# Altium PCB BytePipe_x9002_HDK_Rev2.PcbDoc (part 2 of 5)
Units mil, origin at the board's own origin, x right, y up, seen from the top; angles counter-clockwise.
Board outline 4250 x 4250 mil, 8 copper layers (Top Layer, L2-GND, L3-SIG, L4-GND, L5-PWR, L6-SIG, L7-GND, Bottom Layer), stack 63 mil thick; 296 components, 250 nets, 1198 pads, 2326 vias.
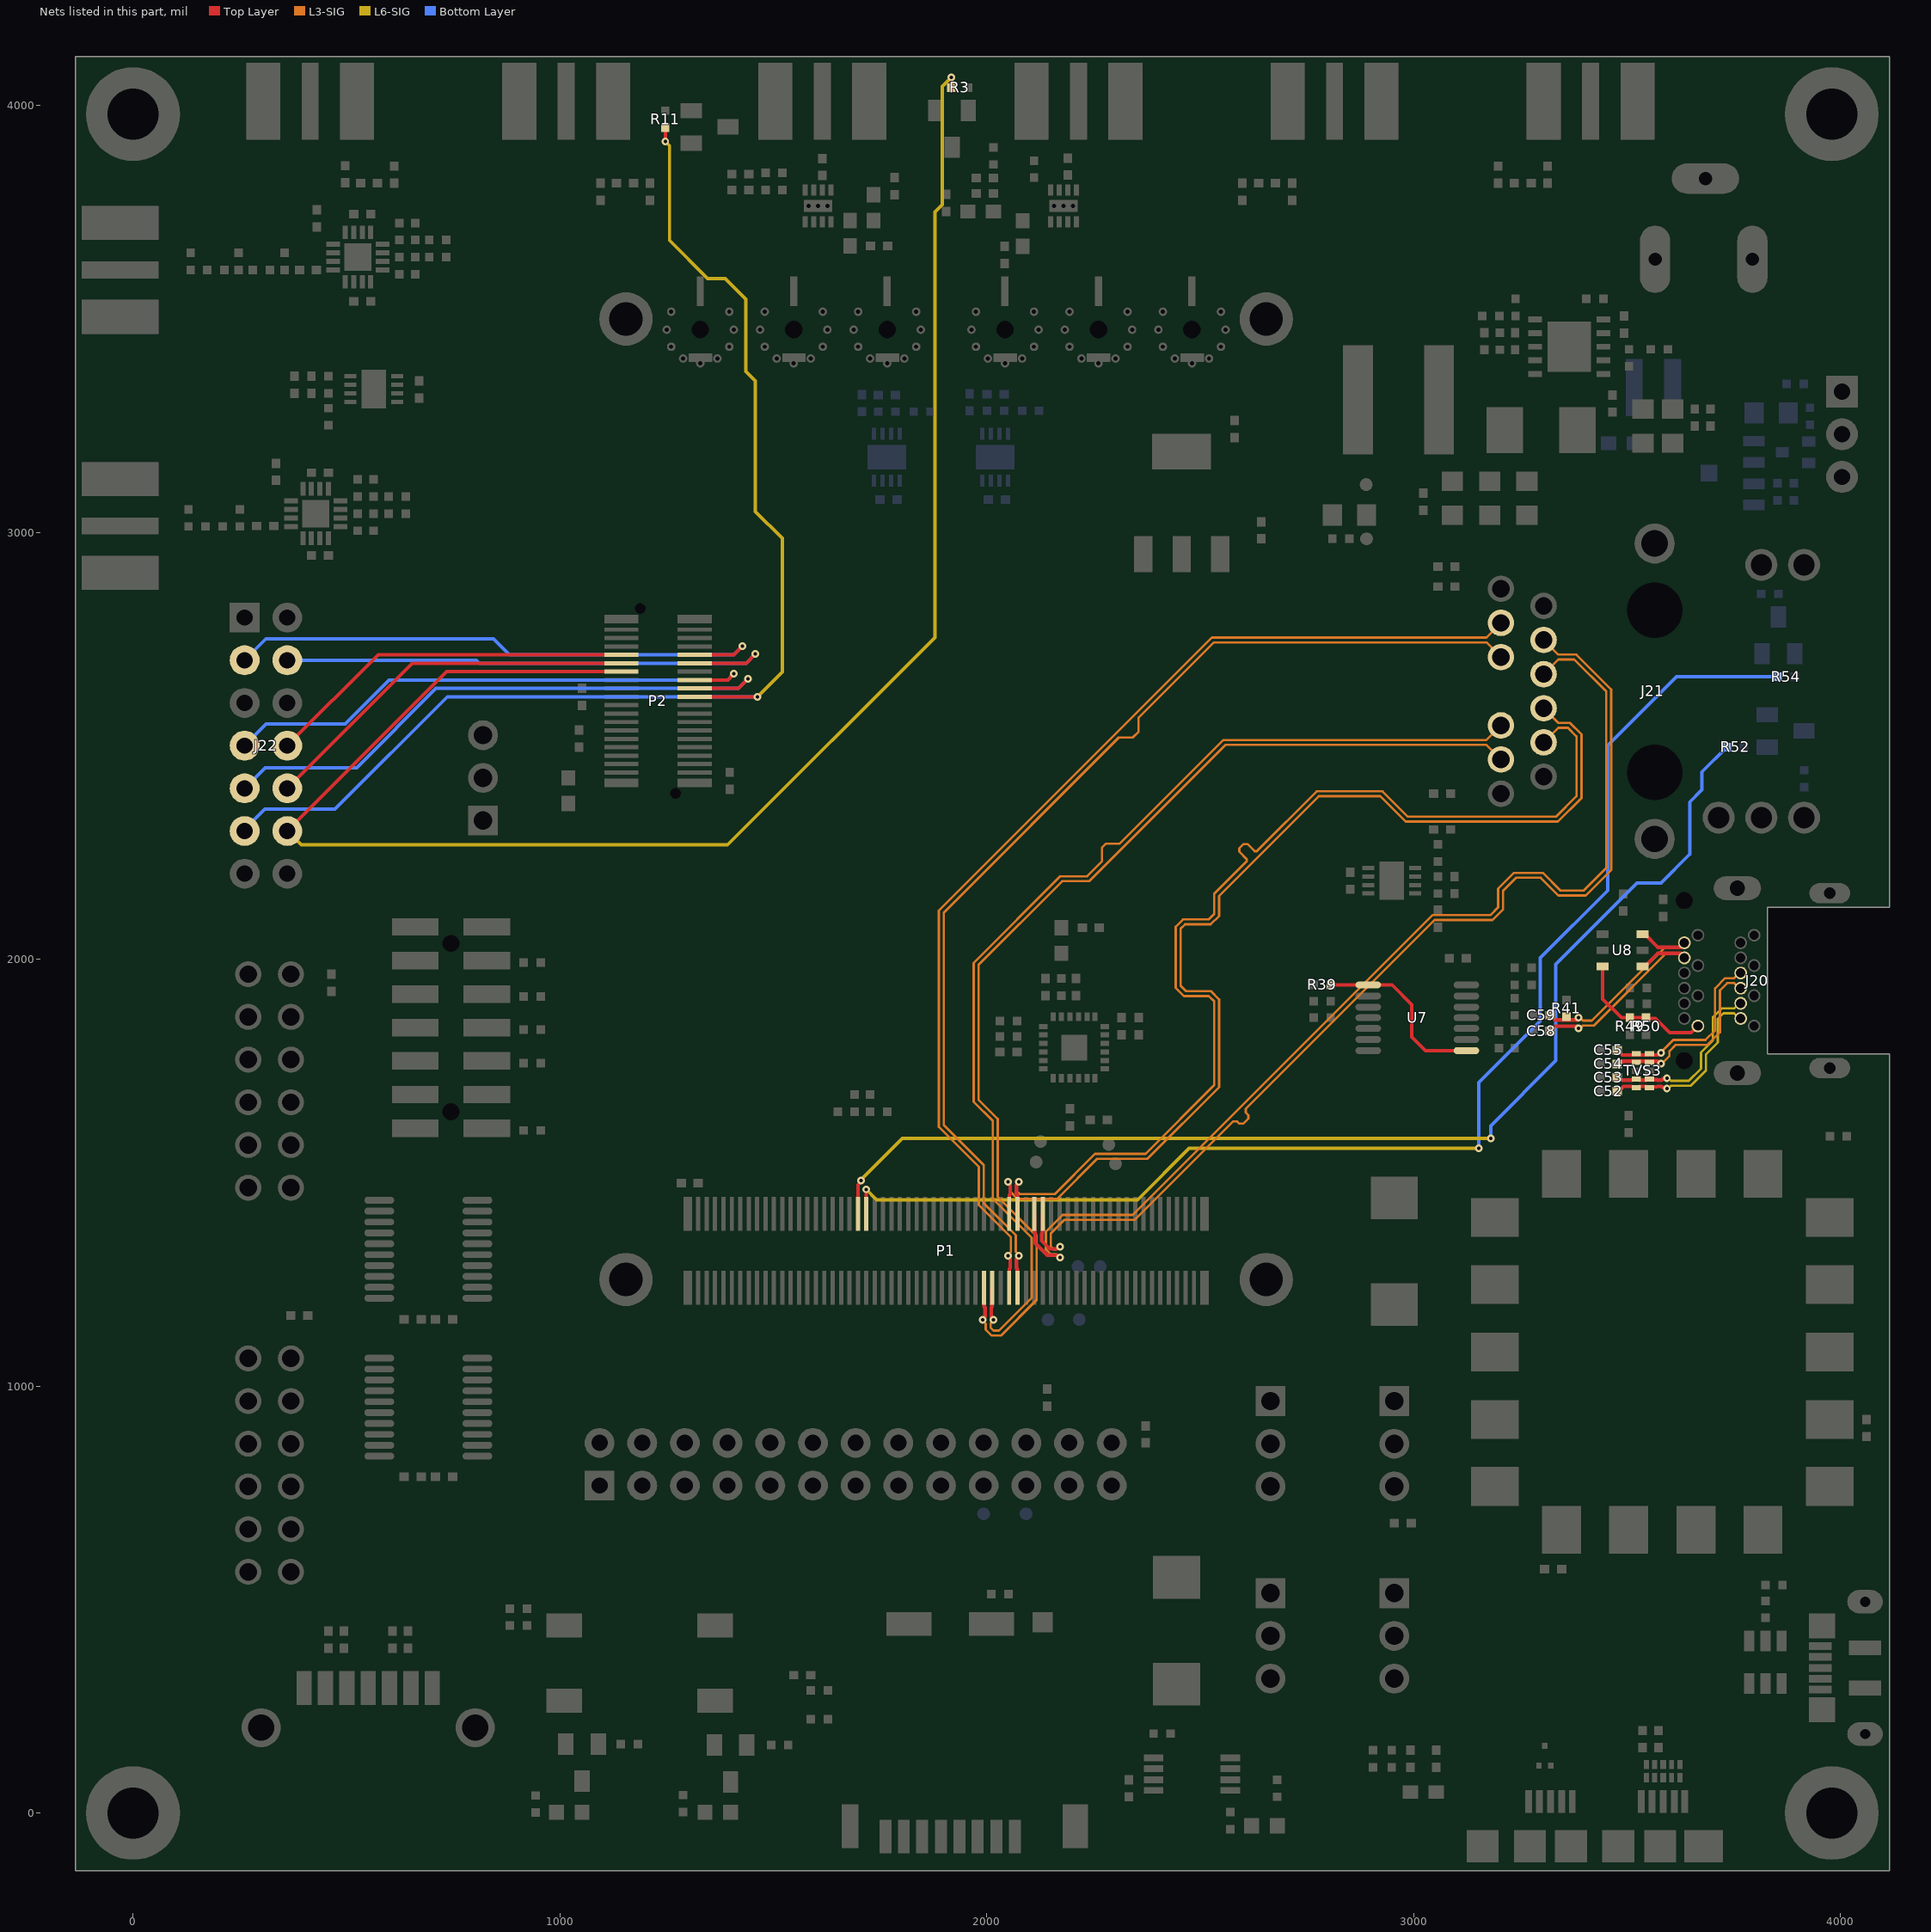
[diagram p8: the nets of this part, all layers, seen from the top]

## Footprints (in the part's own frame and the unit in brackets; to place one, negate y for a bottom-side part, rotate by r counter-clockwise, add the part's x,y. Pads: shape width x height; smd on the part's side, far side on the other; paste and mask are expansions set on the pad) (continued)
SM/SOT323_A [mil]
  rect 24x31 smd mask+3: 1(-25,-31) 2(25,-31) 3(0,31)
  silkscreen extent -45,-5 45,30
SM/SWITCH/E-SWITCH/SPST [mil] "SWITCH TACTILE SPST-NO 0.05A 12V"
  rect 84x56 smd paste+0 mask+3: 1(0,0) 2(354,0) 3(0,176) 4(354,176)
  silkscreen extent -55,-40 409,216, body extent -20,-30 374,206, height 172
SM/TESTPOINT/30MIL [mil]
  round 30 smd paste-15 mask+2: 1(0,0)
SM/TSOP-6_A [mil] "Built for the IP422OCZ6"
  rect 18x28 smd mask+3: 1(37.5,47) 2(0,47) 3(-37.5,47) 4(-37.5,-47) 5(0,-47) 6(37.5,-47)
  silkscreen extent -65,-75 65,75, body extent -57,-46 57,46, height 39
SM/TSSOP14_5X6.4MM_A [mil]
  oval 16x60 smd mask+3: 1(-77,-115) 2(-51,-115) 3(-25,-115) 4(0,-115) 5(25,-115) 6(51,-115) 7(77,-115) 8(77,115) 9(51,115) 10(25,115) 11(0,115) 12(-25,115) 13(-51,115) 14(-77,115)
  silkscreen extent -115,-165 115,165, body extent -98,-126 98,126, height 47
SM/TSSOP20_6.5X6.4MM [mil]
  oval 16x70 smd mask+3: 1(0,0) 2(25.5,0) 3(51,0) 4(76.5,0) 5(102,0) 6(127.5,0) 7(153,0) 8(178.5,0) 9(204,0) 10(229.5,0) 11(229.5,230) 12(204,230) 13(178.5,230) 14(153,230) 15(127.5,230) 16(102,230) 17(76.5,230) 18(51,230) 19(25.5,230) 20(0,230)
  silkscreen extent -25,-50 255,280, body extent -15,-14 245,244, height 47
SM/WSON10/4x4MM_A [mil] ".8mm lead pitch"
  rect 14x32 smd paste+0 mask+3: 1(-64,-80) 2(-32,-80) 3(0,-80) 4(32,-80) 5(64,-80) 6(64,80) 7(32,80) 8(0,80) 9(-32,80) 10(-64,80)
  rect 118x102 smd paste-10 mask+3: 11(0,0)
  silkscreen extent -85,-112 85,90
SWITCH/NIDEC/SPDT/AS1D-2M-10-Z [mil] "SWITCH SLIDE SPDT 50MA 48V"
  rect 75x75 hole 38: 1(0,0)
  round 75 hole 38: 2(0,-100) 3(0,-200)
  silkscreen extent -105,-290 106,99, body extent -98,-287 98,87, height 485

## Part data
C1 C4 C23 C27 C38 C39 C43 C47 C48 C67 C70 C71 C72 C75 C76 C82 C85 C88 C91: "CAP CER 4.7UF 10V X5R 0402", VOLT=10V
C2 C3 C5 C18 C77 C80 C83 C86 C89: "10µF ±20% 10V Ceramic Capacitor X5R 0402 (1005 Metric)", VOLT=10V
C6 C12 C13 C19 C21 C22: "CAP CER 100PF 50V C0G/NP0 0402", VOLT=50V
C7 C20: "CAP CER 1UF 16V X5R 0402", VOLT=16V
C24 C26 C28 C30 C31 C32 C33 C34 C35 C40 C41 C42 C44 C45 C46 C49 C50 C51 C52 C53 C54 C55 C56 C57 C58 C59 C60 C61 C62 C63 C64 C65 C66 C68 C69 C78 C79 C81 C84 C87 C90: "CAP CER 0.1UF 25V X7R 0402", VOLT=25V
C25 C29: "CAP CER 10000PF 50V X7R 0402", VOLT=50V
C36 C37: library part CAP_TANT-D, "CAP TANT 150UF 20% 10V 2917", VOLTS=10V
C73 C74 C97: library part CAP_CERAMIC_0402, "CAP CER 1000PF 50V C0G/NP0 0402", VOLT=50V
C92 C93 C94: "CAP CER 10UF 35V X5R 0805", VOLT=35V
C95 C104: VOLT=50V
C96: "CAP CER 0.1UF 50V X7R 0402", VOLT=50V
C98 C99 C100: "CAP CER 22UF 16V X5R 0805", VOLT=16V
C101: library part CAP_CERAMIC_0402, "CAP CER 10000PF 50V X7R 0402", VOLT=50V
C102: library part CAP_CERAMIC_0402, "CAP CER 47PF 50V C0G/NP0 0402", VOLT=50V
C103: library part CAP_CERAMIC_0402, "CAP CER 4700PF 50V X7R 0402", VOLT=50V
D1: "DIODE SCHOTTKY 60V 5A SMB"
J1: library part CON_100SP_1X3P_MLX_KK100, "Connector Header Through Hole 3 position 0.100\" (2.54mm).  Molex KK 100 Series."
J3 J5 J7 J9 J11 J13 J15 J16: "SMA board edge style, .250\" wide style"
J4 J6 J8 J10 J12 J14: "SMPM Connector Plug, Male Pin 50Ohm Surface Mount Solder. Based off of Amphenol 925-144J-51PT"
J17: "7 Position SATA Plug Connector Solder Surface Mount, Right Angle"
J18: "CONN RCPT USB3.1 MICRO B SMD R/A"
J19: library part CON_HIROSE_MICRO-SD_HINGED, "10 (8 + 2) Position Card Connector Secure Digital - microSD™ Surface Mount, Right Angle Gold"
J20: "DisplayPort, Mini  Receptacle Connector 20 Position Through Hole, Right Angle.."
J21: "1 Port RJ45 Magjack Connector Through Hole 10/100/1000 Base-T, AutoMDIX"
J22: "Connector Header Through Hole 14 position 0.100\" (2.54mm)"
J23: "PIN HEADER, DOUBLE ROW 26 PIN, S"
J24: "Connector Header Surface Mount 14 position 0.079\" (2.00mm)"
J25: "Wurth DC power jack, 2.1mm pin, right angle"
J26: "USB MICRO-B RIGHT ANGLE, MOLEX 1051640001"
J28 J31: "Header, 100 mil, 2x6, Right Angle, PMOD pin out."
JP1 JP2 JP3 JP4: "PIN HEADER, SINGLE ROW 3 PIN STR"
L1 L7 L9 L10: "120 Ohms @ 100MHz 1 Power Line Ferrite Bead 0603 (1608 Metric) 3A 25mOhm"
L2 L3 L5 L6 R10 R39 R40 R42 R100 R101: "RES SMD 0 OHM JUMPER 1/10W 0402"
L4 L8: "FIXED IND 68NH 300MA 800 MOHM"
L11: "Fixed Inductors 4.7uH 20% 5.1A 44.1mOhms AEC-Q200"
LED1 LED2 LED3: "LED-0603"
MH1 MH2 MH3 MH4: "125 mil pad / 78 mil hole"
MH5 MH6 MH7 MH8: "220 mil pad / 120 mil hole (#4 Pan Head Screw)"
P1: library part CON_JAE_WR-120S-VFH30-N1, "0.5 mm pitch, 120 Position Connector Receptacle, Center Strip Contacts Surface Mount Gold."
P2: library part CON_JAE_WR-40SB-VFH30-N1, "0.5 mm pitch, 40 Position Connector Receptacle, Center Strip Contacts Surface Mount Gold, with Alignment Pins."
Q1 Q2 Q3 Q4 Q5 Q6: "Bipolar (BJT) Transistor NPN 40V 200mA 300MHz 300mW Surface Mount SOT-23-3 (TO-236)"
Q7: library part FET_P-CHANNEL_PPAK-SO-8, "P-Channel 20 V 60A (Tc) 6.25W (Ta), 104W (Tc) Surface Mount PowerPAK® SO-8"
Q8: "FET, N-Channel, SC70/SOT323"
R1 R3 R4 R11 R77 R78 R79 R86 R88: "RES SMD 10K OHM 1% 1/10W 0402"
R6 R7 R18 R19: "RES SMD 127 OHM 1% 1/10W 0402"
R8 R9 R12 R20 R21 R22 R37 R49 R55 R56 R57 R58 R59 R61: "RES SMD 39 OHM 1% 1/10W 0402"
R13 R14 R15 R23 R24 R43 R44: "RES 49.9 OHM 1% 1/10W 0402"
R16 R17 R25 R26: "RES SMD 150 OHM 1% 1/10W 0402"
R27 R83: "RES SMD 1K OHM 1% 1/10W 0402"
R30 R31 R51 R53 R65 R69: "RES SMD 240 OHM 1% 1/10W 0402"
R32: "RES 2 OHM 1% 1/10W 0402 SMD"
R35 R36 R62: "RES SMD 4.7K OHM 1% 1/10W 0402"
R38 R41 R50 R52 R54 R60 R68 R70 R85: "RES SMD 100K OHM 1% 1/10W 0402"
R45 R46: "RES SMD 1M OHM 1% 1/10W 0402"
R47: "RES SMD 1.5K OHM 1% 1/10W 0402"
R48: "RES SMD 2.49K OHM 1% 1/10W 0402"
R66: "RES 120K OHM 1% 1/10W 0402 SMD"
R67 R72: "RES SMD 78.7K OHM 1% 1/10W 0402"
R71: "RES SMD 140K OHM 1% 1/10W 0402"
R73 R75: "RES SMD 200K OHM 1% 1/10W 0402"
R74 R76: "RES SMD 64.9K OHM 1% 1/10W 0402"
R80 R102 R103: "DNP"
R81: "RES SMD 0 OHM JUMPER 1/8W 0805"
R82: "RES SMD 52.3K OHM 1% 1/10W 0402"
R84: "RES SMD 2 KOHM 1% 1/5W 0402"
R87: "RES SMD 16.9K OHM 1% 1/10W 0402"
SW1: "Tactile Switch SPST-NO Top Actuated Surface Mount"
SW2: library part SWITCH_SLIDE_NIDEC_SPDT, "SWITCH SLIDE SPDT 50MA 48V"
TVS1 TVS3: "TVS DIODE 5.5V 14V 10SON"
TVS2: "TVS DIODE 5.5V 8V SOT3"
U1 U2: "RF Amplifier 50-4000MHz NF .66dB Gain 16.5dB @1.9GHz"
U3 U4: "IC CLK BUFFER 1:4 7GHZ 16LFCSP"
U5: "Power Switch/Driver 1:1 N-Channel 1.5A 8-MSOP"
U6: "IC Programable Clock Generator"
U7: "1/1 Transceiver Full LVDS 14-TSSOP"
U8: "Dual USB ESD Protection"
U9: "SMT Programming module for Xilinx FPGAs."
U10 U11: "IC TRNSLTR BIDIRECTIONAL 20VQFN"
U12: "Clamp Ipp Tvs Diode Surface Mount SOT-23-6."
U13: "Linear Voltage Regulator IC 3.3V Output 1A SOT-223-3"
U14 U15 U16 U17: "Linear Voltage Regulator IC  1 Output  500mA 8-LFCSP-WD (3x3)"
U18: "4.5-V to 60-V Input, 5-A, Step-Down DC-DC Converter with Soft-Start and Eco-mode"

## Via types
v1: diameter 18, hole 8, Top Layer to Bottom Layer, tented both sides, 2283 vias
v2: diameter 20, hole 10, Top Layer to Bottom Layer, tented both sides, 39 vias
v3: diameter 16, hole 8, Top Layer to Bottom Layer, tented both sides, 4 vias

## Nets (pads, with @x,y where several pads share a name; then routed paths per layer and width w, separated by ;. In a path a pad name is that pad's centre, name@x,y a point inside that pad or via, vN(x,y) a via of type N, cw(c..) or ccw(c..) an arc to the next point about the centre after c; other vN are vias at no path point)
AGPIO_1: J22.7 P2.16 | length 1313.8
  Top Layer w8: P2.16@1316.61,2654.21 1393.09,2654.21 1407.88,2669 v1(1408,2669)
  Bottom Layer w8: J22.7@261.5,2500.5 312.25,2551.25 497.29,2551.25 600.25,2654.21 1393.21,2654.21 v1(1408,2669)
AGPIO_2: J22.8 P2.09 | length 870
  Top Layer w8: J22.8@361.5,2500.5 574.27,2713.27 P2.09@1143.39,2713.27
AGPIO_3: J22.9 P2.18 | length 1419.4
  Top Layer w8: P2.18@1316.61,2634.53 1418.53,2634.53 v1(1441,2657)
  Bottom Layer w8: J22.9@261.5,2400.5 309.93,2448.93 524.35,2448.93 709.95,2634.53 1418.53,2634.53 v1(1441,2657)
AGPIO_4: J22.10 P2.11 | length 903.3
  Top Layer w8: J22.10@361.5,2400.5 654.58,2693.58 P2.11@1143.39,2693.58
AGPIO_5: J22.11 P2.20 R11.1 | length 2975.3
  Top Layer w8: J22.11@261.5,2300.5 J22.11@261.5,2304.37 ; v1(1247,3916) R11.1@1247,3948 ; P2.20@1316.61,2614.84 v1(1463.16,2614.84)
  L6-SIG w8: v1(1247,3916) 1257,3906 1257,3684 1346,3595 1387,3595 1436,3546 1436,3377.31 1458,3355.31 1458,3049 1521,2986 1521,2672.68 v1(1463.16,2614.84)
  Bottom Layer w8: J22.11@261.5,2304.37 308.55,2351.41 472.88,2351.41 736.31,2614.84 v1(1463.16,2614.84)
AGPIO_6: J22.12 P2.13 R3.1 | length 4020.6
  Top Layer w8: J22.12@361.5,2300.5 734.9,2673.9 P2.13@1143.39,2673.9 ; R3.1@1917,4042 v1(1917,4066)
  L6-SIG w8: J22.12@361.5,2300.5 394,2268 1393,2268 1879,2754 1879,3751 1896,3768 1896,4045 v1(1917,4066)
AUXADC_0: J22.3 P2.10 | length 1331.1
  Top Layer w8: P2.10@1316.61,2713.27 1407.27,2713.27 v1(1428,2734)
  Bottom Layer w8: J22.3@261.5,2700.5 311.34,2750.34 844.64,2750.34 881.71,2713.27 1407.27,2713.27 v1(1428,2734)
AUXADC_1: J22.4 P2.12 | length 1258.5
  Top Layer w8: P2.12@1316.61,2693.58 1436.58,2693.58 v1(1458,2715)
  Bottom Layer w8: J22.4@361.5,2700.5 804.06,2700.5 810.97,2693.58 1436.58,2693.58 v1(1458,2715)
DP_HPD: J20.2 R49.2 R50.2 U8.3 | length 339.2
  Top Layer w8: U8.3@3443,1983.5 3443,1907 3487,1863 R49.2@3507,1863 R50.2@3545,1863 3547,1861 3567,1861 3600.26,1827.74 3650.26,1827.74 J20.2@3666.22,1843.7
DP_RE_N: R39.1 U7.1 U7.8 | length 426.3
  Top Layer w8: R39.1@2806,1940 U7.1@2894,1940 2950,1940 2996,1894 2996,1818 3028,1786 U7.8@3124,1786
DP_TX2_N: C55.2 J20.11 TVS3.5 TVS3.6 | length 427.7
  Top Layer w8.75: C55.2@3480,1787 3480,1785 3489.1,1775.9 3522.03,1775.9 TVS3.6@3524.5,1778.37 ; TVS3.6@3525.58,1775.9 3550.61,1775.9 TVS3.5@3553.08,1778.37 3555.58,1775.88 3571.95,1775.88 3577.08,1781 v1(3579.58,1781)
  L3-SIG w5.5: v1@3582,1784.38 3608.62,1811 3684,1811 3706.5,1833.5 3706.5,1932.01 3730.24,1955.75 3751.14,1955.75 3763.11,1967.72 J20.11@3766.61,1967.72
DP_TX2_P: C54.2 J20.9 TVS3.4 TVS3.7 | length 439.3
  Top Layer w8.75: C54.2@3480,1754.67 3481.3,1755.97 3481.3,1757.97 3483.62,1760.29 3490.89,1760.29 3491.75,1761.15 3522.03,1761.15 TVS3.7@3524.5,1758.68 ; TVS3.7@3525.58,1761.15 TVS3.4@3549.44,1761.15 ; TVS3.4@3549.47,1761.12 3550.64,1761.12 TVS3.4@3553.08,1758.68 3555.52,1761.12 3571.95,1761.12 3577.08,1756 v1(3579.58,1756)
  L3-SIG w5.5: v1@3582,1756 3582.1,1756 3599.75,1773.65 3599.75,1784.75 3614.5,1799.5 3688.76,1799.5 3718,1828.74 3718,1927.25 3735,1944.25 3751.14,1944.25 3763.11,1932.28 J20.9@3766.61,1932.28
DP_TX3_N: C53.2 J20.5 TVS3.2 TVS3.9 | length 420.2
  Top Layer w8.75: C53.2@3481,1723.33 3480,1723.33 3480,1721.33 3483.62,1717.71 3487.97,1717.71 3488.75,1716.92 3511.44,1716.92 3512.21,1717.69 3520.46,1717.69 TVS3.9@3522.08,1719.31 3527.08,1719.31 3529.55,1716.85 TVS3.2@3544.58,1716.85 ; TVS3.2@3553.08,1719.31 3554.71,1717.69 3570.58,1717.69 3571.43,1716.85 3581.65,1716.85 3584.56,1719.75 3591.85,1719.75 v1(3593.62,1721.52)
  L6-SIG w5.5: v1(3593.62,1721.52) 3596.84,1721.52 3603.09,1715.27 3610.87,1715.27 3645.02,1715.27 3673.5,1743.75 3673.5,1781.76 3701.5,1809.76 3701.5,1864.76 3721.62,1884.88 3751.14,1884.88 3763.11,1896.85 J20.5@3766.61,1896.85
DP_TX3_P: C52.2 J20.3 TVS3.1 TVS3.10 | length 415
  Top Layer w8.75: C52.2@3480,1691 3481,1691 3492.17,1702.17 3511.29,1702.17 3512.21,1701.25 3520.46,1701.25 TVS3.10@3522.08,1699.63 ; TVS3.10@3527.08,1699.63 3529.55,1702.1 TVS3.1@3544.58,1702.1 ; TVS3.1@3553.08,1699.63 3554.71,1701.25 3570.58,1701.25 3571.43,1702.1 3581.75,1702.1 3584.56,1699.29 3591.85,1699.29 v1(3593.62,1697.52)
  L6-SIG w5.5: v1(3593.62,1697.52) 3596.84,1697.52 3603.09,1703.77 3615.63,1703.77 3649.79,1703.77 3685,1738.99 3685,1777 3713,1805 3713,1860 3726.38,1873.38 3751.14,1873.38 3763.11,1861.42 J20.3@3766.61,1861.42
DPAUX_C_N: C59.2 J20.18 R41.1 U8.6 | length 496.9
  Top Layer w8.75: C59.2@3320,1869 3321,1869 3326.62,1863.38 3326.62,1863 3331.75,1857.88 v1@3385,1857.88 ; U8.6@3537,2058.5 3542,2058.5 3572.12,2028.38 J20.18@3625.58,2028.38
  L3-SIG w5.5: v1(3387,1863) 3389.72,1863 3396.47,1856.25 3417.87,1856.25 3588.24,2026.62 3619.25,2026.62 3631.22,2038.58 J20.18@3634.72,2038.58
DPAUX_C_P: C58.2 J20.16 U8.4 | length 496.9
  Top Layer w8.75: C58.2@3320,1832 3321,1832 3326.62,1837.62 3326.62,1838 3331.75,1843.12 v1@3385,1843.12 ; U8.4@3537,1983.5 3542,1983.5 3572.12,2013.62 J20.16@3625.58,2013.62
  L3-SIG w5.5: v1(3387,1838) 3389.72,1838 3396.47,1844.75 3422.63,1844.75 3593,2015.12 3619.25,2015.12 3631.22,2003.15 J20.16@3634.72,2003.15
ETH_LED0: P1.81 R52.2 | length 2776.9
  Top Layer w8: P1.81@1698.31,1403.61 1698.65,1403.96 1698.65,1472 1705.83,1479.18 v1(1705.83,1481.69)
  L6-SIG w8: v1(1705.83,1481.69) 1705.83,1483.25 1802.58,1580 v1(3181,1580)
  Bottom Layer w8: v1(3181,1580) 3181,1609.73 3333.68,1762.41 3333.68,1988.68 3524,2179 3580,2179 3647,2246 3647,2368 3676,2397 3676,2439 R52.2@3734,2497
ETH_LED1: P1.79 R54.2 | length 3086
  Top Layer w8: P1.79@1717.99,1403.61 v1(1718,1461)
  L6-SIG w8: v1(1718,1461) 1742.27,1436.73 2353.77,1436.73 2474.03,1557 v1(3153,1557)
  Bottom Layer w8: v1(3153,1557) 3153,1711 3297,1855 3297,2003 3455,2161 3455,2501 3616,2662 R54.2@3853,2662
ETH_MD1_N: J21.10 P1.50 | length 2558.1
  Top Layer w8.75: P1.50@2013.27,1230.39 2012.64,1229.76 2012.64,1185.88 2010.77,1184.01 2010.77,1163.07 2015.89,1157.95 v1(2015.89,1155.44)
  L3-SIG w5.5: v1(2015.89,1155.44) 2015.89,1152.72 2009.14,1145.97 2009.14,1137.17 2016.31,1130 2028.74,1130 2105.67,1206.94 2105.67,1347.32 2014.5,1438.49 2014.5,1621.24 1969.5,1666.24 1969.5,1991.5 2172.5,2194.5 2235.24,2194.5 2270,2229.26 2270,2261 2280,2271 2311.74,2271 2554.49,2513.75 3170.75,2513.75 J21.10@3205,2548 J21.10@3203,2548
ETH_MD1_P: J21.11 P1.52 | length 2561.8
  Top Layer w8.75: v1(1990.89,1155.44) 1990.89,1157.95 1996.02,1163.07 1996.02,1184.07 1994.21,1185.88 P1.52@1994.21,1235.87
  L3-SIG w5.5: v1(1990.89,1155.44) 1990.89,1152.72 1997.64,1145.97 1997.64,1132.41 2011.55,1118.5 2033.5,1118.5 2117.17,1202.17 2117.17,1352.08 2026,1443.26 2026,1626 1981,1671 1981,1986.74 2177.26,2183 2240,2183 2559.25,2502.25 3170.75,2502.25 J21.11@3205,2468
ETH_MD2_N: J21.5 P1.43 | length 2556.1
  Top Layer w8.75: P1.43@2072.32,1403.61 2071.7,1404.24 2071.7,1448.12 2069.86,1449.96 2069.86,1470.9 2075.01,1476.05 v1(2075.01,1478.56)
  L3-SIG w5.5: v1(2075.01,1478.56) 2075.01,1475.83 2068.26,1469.08 2068.26,1458.74 2077,1450 2160,1450 2254,1544 2372.07,1544 2533,1704.93 2533,1901.26 2520.5,1913.76 2462.24,1913.76 2443,1933 2443,2076.26 2460,2093.26 2520,2093.26 2533,2106.26 2533,2153.26 2609.59,2229.85 2609.59,2234.41 2592,2252 2592,2260 2602,2270 2611,2270 2628,2253 2632.74,2253 2773.24,2393.5 2927.32,2393.5 2986.82,2334 3333.74,2334 3382,2382.26 3382,2522.25 3362,2542.25 3339.25,2542.25 J21.5@3305,2508
ETH_MD2_P: J21.4 P1.45 | length 2556.6
  Top Layer w8.75: v1(2050.01,1478.56) 2050.01,1476.05 2055.11,1470.96 2055.11,1449.96 2053.26,1448.12 2053.26,1404.24 P1.45@2052.64,1403.61
  L3-SIG w5.5: v1(2050.01,1478.56) 2050.01,1475.83 2056.76,1469.08 2056.76,1453.97 2072.24,1438.5 2164.76,1438.5 2258.76,1532.5 2376.84,1532.5 2544.5,1700.16 2544.5,1906.03 2525.26,1925.26 2467,1925.26 2454.5,1937.76 2454.5,2071.5 2464.76,2081.76 2524.76,2081.76 2544.5,2101.5 2544.5,2148.5 2778,2382 2922.55,2382 2982.05,2322.5 3338.5,2322.5 3393.5,2377.5 3393.5,2527.01 3366.76,2553.75 3339.25,2553.75 J21.4@3305,2588
ETH_MD3_N: J21.2 P1.37 | length 2556.8
  Top Layer w8.75: v1(2172.39,1326.8) 2169.88,1326.8 2164.76,1321.68 2148,1321.68 2128.91,1340.76 2128.91,1357.27 2130.75,1359.11 P1.37@2130.75,1402.99 ; P1.37@2130.75,1402.99 P1.37@2131.38,1403.61 P1.37@2130.75,1402.99
  L3-SIG w5.5: v1(2172.39,1326.8) 2169.67,1326.8 2162.92,1320.05 2157.95,1320.05 2150.23,1327.77 2150.23,1357.34 2182.53,1389.64 2346.9,1389.64 2577.26,1620 2587,1620 2592,1615 2601,1615 2613,1627 2613,1635 2607,1641 2607,1649.74 3049.26,2092 3185,2092 3210,2117 3210,2161 3240,2191 3298,2191 3339.5,2149.5 3403.5,2149.5 3463,2209 3463,2632.26 3381.51,2713.75 3339.25,2713.75 J21.2@3305,2748
ETH_MD3_P: J21.3 P1.39 | length 2556.1
  Top Layer w8.75: P1.39@2111.69,1403.61 2112.32,1402.99 2112.32,1359.11 2114.16,1357.27 2114.16,1334.65 2141.89,1306.93 2164.76,1306.93 2169.88,1301.8 v1(2172.39,1301.8)
  L3-SIG w5.5: v1(2172.39,1301.8) 2169.67,1301.8 2162.92,1308.55 2150.37,1308.55 2138.73,1320.2 2138.73,1362.1 2177.77,1401.14 2342.14,1401.14 3044.5,2103.5 3180.24,2103.5 3198.5,2121.76 3198.5,2165.76 3235.24,2202.5 3302.76,2202.5 3344.26,2161 3398.74,2161 3451.5,2213.76 3451.5,2627.5 3376.75,2702.25 3339.25,2702.25 J21.3@3305,2668
ETH_MD4_N: J21.9 P1.44 | length 2556.1
  Top Layer w8.75: P1.44@2072.32,1230.39 2071.7,1231.01 2071.7,1274.89 2069.86,1276.73 2069.86,1297.67 2075.01,1302.82 v1(2075.01,1305.33)
  L3-SIG w5.5: v1(2075.01,1305.33) 2075.01,1308.05 2068.26,1314.8 2068.26,1353.52 1993,1428.78 1993,1518.42 1899.5,1611.92 1899.5,2109.5 2309.5,2519.5 2342.5,2519.5 2356,2533 2356,2566 2532.25,2742.25 3170.75,2742.25 J21.9@3205,2708
ETH_MD4_P: J21.8 P1.46 | length 2555.8
  Top Layer w8.75: v1(2050.01,1305.33) 2050.01,1302.82 2055.11,1297.73 2055.11,1276.73 2053.26,1274.89 2053.26,1231.01 P1.46@2052.64,1230.39
  L3-SIG w5.5: v1(2050.01,1305.33) 2050.01,1308.05 2056.76,1314.8 2056.76,1348.75 1981.5,1424.01 1981.5,1513.66 1888,1607.16 1888,2114.26 2527.49,2753.75 3170.75,2753.75 J21.8@3205,2788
